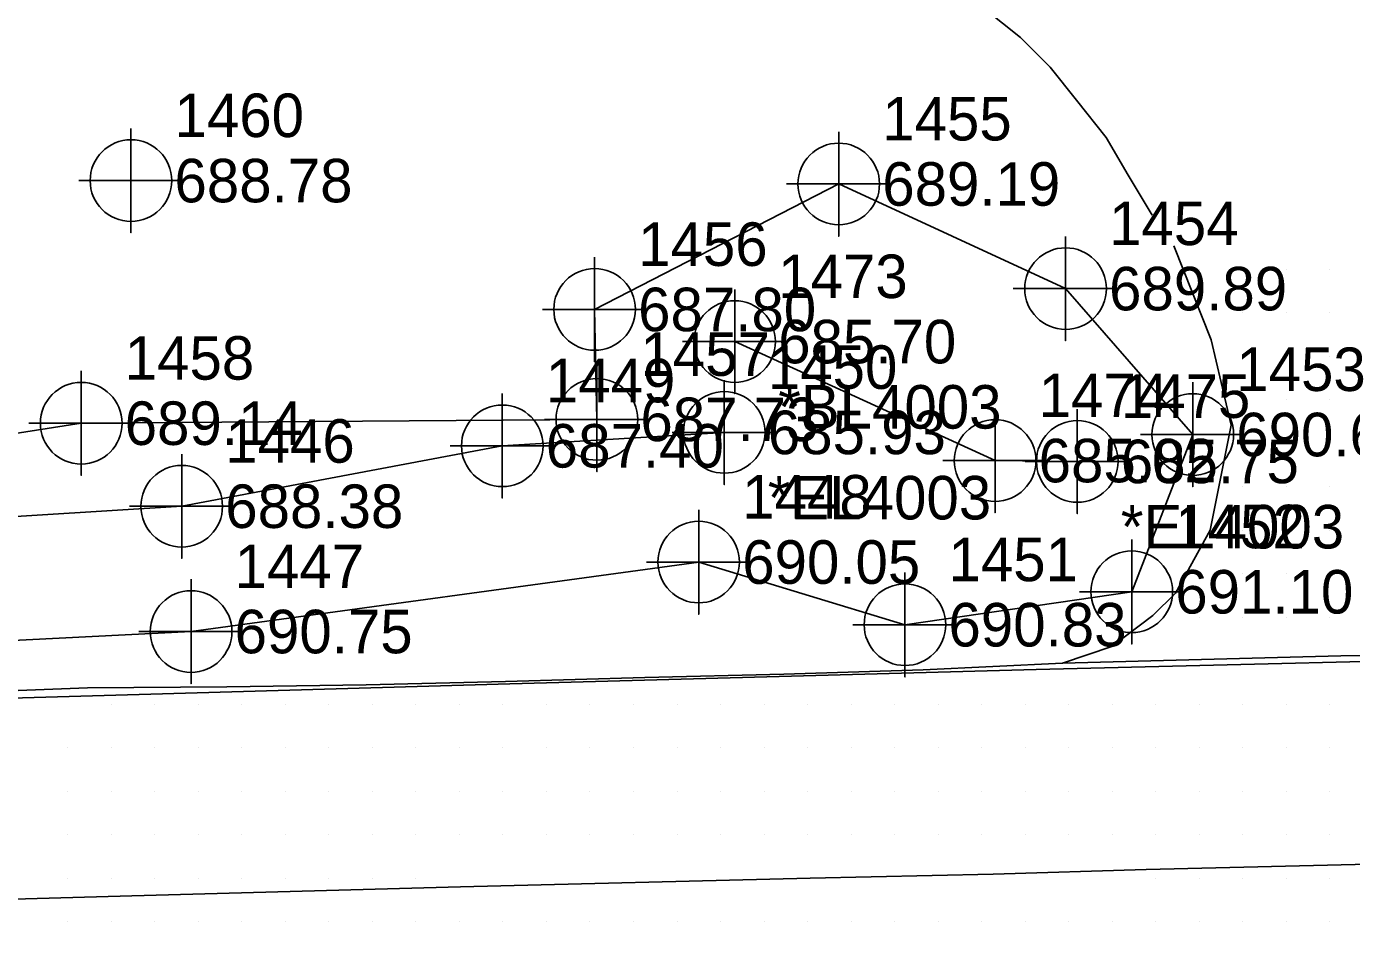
# Model space of a CAD drawing. Extents: x 1755643 to 1760494, y 736519 to 737621.
# Drawn here: x 1757941.4 to 1758017.5, y 736988 to 737040.2 of the extents above; entities that cross this region are included whole.
import ezdxf

# ---------------------------------------------------------------- set-up
doc = ezdxf.new("R2010")
doc.units = 0
for name, color, linetype in [('Exist Horizontal Alignment Curve and Spiral Data', 7, 'Continuous'), ('Exist Railroads Standard Gauge', 7, 'Continuous'), ('Exist Roads EOT', 7, 'Continuous'), ('Old_Level_1', 7, 'Continuous'), ('Old_Level_10', 7, 'Continuous'), ('Old_Level_2', 7, 'Continuous'), ('Old_Level_3', 7, 'Continuous'), ('Prop Corridor Linear Feature', 7, 'Continuous'), ('Prop Dimension', 7, 'Continuous'), ('Prop EOT Dash', 7, 'Continuous'), ('Prop Horizontal Alignment Direction Label', 7, 'Continuous'), ('Prop Lane Lines', 7, 'Continuous'), ('Prop Paved Shoulder', 7, 'Continuous'), ('Scratch_Level_1', 7, 'Continuous'), ('Scratch_Level_2', 7, 'Continuous'), ('Scratch_Level_5', 7, 'Continuous'), ('Scratch_Level_6', 7, 'Continuous'), ('Scratch_Level_9', 7, 'Continuous')]:
    doc.layers.add(name, color=color, linetype=linetype)

msp = doc.modelspace()

# ---------------------------------------------------------------- linework, layer by layer
at = {"layer": 'Exist Horizontal Alignment Curve and Spiral Data'}
msp.add_lwpolyline([(1757947.389, 737034.333), (1757947.389, 737028.333), (1757947.389, 737031.333), (1757950.389, 737031.333), (1757944.389, 737031.333)], dxfattribs=at)
msp.add_circle((1757947.389, 737031.333), 2.344, dxfattribs=at)
at = {"layer": 'Exist Railroads Standard Gauge'}
msp.add_lwpolyline([(1758006.043, 737029.342), (1758004.657, 737031.64), (1758003.404, 737033.807), (1758001.694, 737035.948), (1758000.175, 737037.856), (1757998.469, 737039.562), (1757996.412, 737041.197), (1757991.599, 737043.919), (1757989.449, 737044.86), (1757987.274, 737045.06), (1757962.295, 737044.106), (1757961.554, 737063.076)], dxfattribs=at)
at = {"layer": 'Old_Level_10'}
for points in [[(1757982.062, 737025.084), (1757982.062, 737019.084), (1757982.062, 737022.084), (1757985.062, 737022.084), (1757979.062, 737022.084)], [(1757981.467, 737019.866), (1757981.467, 737013.866), (1757981.467, 737016.866), (1757984.467, 737016.866), (1757978.467, 737016.866)], [(1757968.716, 737019.095), (1757968.716, 737013.095), (1757968.716, 737016.095), (1757971.716, 737016.095), (1757965.716, 737016.095)], [(1757997.02, 737018.248), (1757997.02, 737012.248), (1757997.02, 737015.248), (1758000.02, 737015.248), (1757994.02, 737015.248)], [(1758001.739, 737018.198), (1758001.739, 737012.198), (1758001.739, 737015.198), (1758004.739, 737015.198), (1757998.739, 737015.198)], [(1757950.306, 737015.625), (1757950.306, 737009.625), (1757950.306, 737012.625), (1757953.306, 737012.625), (1757947.306, 737012.625)]]:
    msp.add_lwpolyline(points, dxfattribs=at)
for centre in [(1757982.062, 737022.084), (1757981.467, 737016.866), (1757968.716, 737016.095), (1757997.02, 737015.248), (1758001.739, 737015.198), (1757950.306, 737012.625)]:
    msp.add_circle(centre, 2.344, dxfattribs=at)
at = {"layer": 'Prop Corridor Linear Feature'}
msp.add_lwpolyline([(1758000.882, 737003.602), (1758008.879, 737003.814), (1758016.875, 737004.021), (1758024.873, 737004.152), (1758028.534, 737004.265), (1758030.505, 737004.507)], dxfattribs=at)
at = {"layer": 'Prop Dimension'}
for points in [[(1757982.062, 737022.084), (1757997.02, 737015.248), (1758001.739, 737015.198)], [(1757921.064, 737010.807), (1757950.306, 737012.625), (1757968.716, 737016.095), (1757981.467, 737016.866)]]:
    msp.add_lwpolyline(points, dxfattribs=at)
at = {"layer": 'Prop Lane Lines'}
for points in [[(1757988.037, 737034.139), (1757988.037, 737028.139), (1757988.037, 737031.139), (1757991.037, 737031.139), (1757985.037, 737031.139)], [(1758001.065, 737028.127), (1758001.065, 737022.127), (1758001.065, 737025.127), (1758004.065, 737025.127), (1757998.065, 737025.127)], [(1757974.018, 737026.93), (1757974.018, 737020.93), (1757974.018, 737023.93), (1757977.018, 737023.93), (1757971.018, 737023.93)], [(1757944.532, 737020.395), (1757944.532, 737014.395), (1757944.532, 737017.395), (1757947.532, 737017.395), (1757941.532, 737017.395)], [(1757974.149, 737020.615), (1757974.149, 737014.615), (1757974.149, 737017.615), (1757977.149, 737017.615), (1757971.149, 737017.615)], [(1758008.37, 737019.744), (1758008.37, 737013.744), (1758008.37, 737016.744), (1758011.37, 737016.744), (1758005.37, 737016.744)], [(1757979.995, 737012.419), (1757979.995, 737006.419), (1757979.995, 737009.419), (1757982.995, 737009.419), (1757976.995, 737009.419)], [(1758004.867, 737010.71), (1758004.867, 737004.71), (1758004.867, 737007.71), (1758007.867, 737007.71), (1758001.867, 737007.71)], [(1757991.841, 737008.818), (1757991.841, 737002.818), (1757991.841, 737005.818), (1757994.841, 737005.818), (1757988.841, 737005.818)], [(1757950.843, 737008.426), (1757950.843, 737002.426), (1757950.843, 737005.426), (1757953.843, 737005.426), (1757947.843, 737005.426)]]:
    msp.add_lwpolyline(points, dxfattribs=at)
for centre in [(1757988.037, 737031.139), (1758001.065, 737025.127), (1757974.018, 737023.93), (1757944.532, 737017.395), (1757974.149, 737017.615), (1758008.37, 737016.744), (1757979.995, 737009.419), (1758004.867, 737007.71), (1757991.841, 737005.818), (1757950.843, 737005.426)]:
    msp.add_circle(centre, 2.344, dxfattribs=at)
at = {"layer": 'Scratch_Level_1'}
msp.add_lwpolyline([(1757864.939, 737000.079), (1757872.936, 737000.271), (1757880.928, 737000.627), (1757888.921, 737000.805), (1757896.919, 737000.945), (1757904.914, 737001.227), (1757912.914, 737001.293), (1757920.91, 737001.55), (1757928.913, 737001.535), (1757936.905, 737001.889), (1757944.899, 737002.192), (1757952.901, 737002.259), (1757960.901, 737002.367), (1757968.898, 737002.553), (1757976.895, 737002.778), (1757984.893, 737002.981), (1757992.889, 737003.22), (1758000.882, 737003.602)], dxfattribs=at)
at = {"layer": 'Scratch_Level_2'}
for p, q in [((1758008.75, 737026.25), (1758008.75, 737026.25)), ((1758011.25, 737026.25), (1758011.25, 737026.25)), ((1758013.75, 737026.25), (1758013.75, 737026.25)), ((1758016.25, 737026.25), (1758016.25, 737026.25)), ((1758011.25, 737023.75), (1758011.25, 737023.75)), ((1758013.75, 737023.75), (1758013.75, 737023.75)), ((1758016.25, 737023.75), (1758016.25, 737023.75)), ((1758011.25, 737021.25), (1758011.25, 737021.25)), ((1758013.75, 737021.25), (1758013.75, 737021.25)), ((1758016.25, 737021.25), (1758016.25, 737021.25)), ((1758011.25, 737018.75), (1758011.25, 737018.75)), ((1758013.75, 737018.75), (1758013.75, 737018.75)), ((1758016.25, 737018.75), (1758016.25, 737018.75)), ((1758011.25, 737016.25), (1758011.25, 737016.25)), ((1758013.75, 737016.25), (1758013.75, 737016.25)), ((1758016.25, 737016.25), (1758016.25, 737016.25)), ((1758011.25, 737013.75), (1758011.25, 737013.75)), ((1758013.75, 737013.75), (1758013.75, 737013.75)), ((1758016.25, 737013.75), (1758016.25, 737013.75)), ((1758011.25, 737011.25), (1758011.25, 737011.25)), ((1758013.75, 737011.25), (1758013.75, 737011.25)), ((1758016.25, 737011.25), (1758016.25, 737011.25)), ((1758008.75, 737008.75), (1758008.75, 737008.75)), ((1758011.25, 737008.75), (1758011.25, 737008.75)), ((1758013.75, 737008.75), (1758013.75, 737008.75)), ((1758016.25, 737008.75), (1758016.25, 737008.75)), ((1758008.75, 737006.25), (1758008.75, 737006.25)), ((1758011.25, 737006.25), (1758011.25, 737006.25)), ((1758013.75, 737006.25), (1758013.75, 737006.25)), ((1758016.25, 737006.25), (1758016.25, 737006.25)), ((1757946.25, 737001.25), (1757946.25, 737001.25)), ((1757948.75, 737001.25), (1757948.75, 737001.25)), ((1757951.25, 737001.25), (1757951.25, 737001.25)), ((1757953.75, 737001.25), (1757953.75, 737001.25)), ((1757956.25, 737001.25), (1757956.25, 737001.25)), ((1757958.75, 737001.25), (1757958.75, 737001.25)), ((1757961.25, 737001.25), (1757961.25, 737001.25)), ((1757963.75, 737001.25), (1757963.75, 737001.25)), ((1757966.25, 737001.25), (1757966.25, 737001.25)), ((1757968.75, 737001.25), (1757968.75, 737001.25)), ((1757971.25, 737001.25), (1757971.25, 737001.25)), ((1757973.75, 737001.25), (1757973.75, 737001.25)), ((1757976.25, 737001.25), (1757976.25, 737001.25)), ((1757978.75, 737001.25), (1757978.75, 737001.25)), ((1757981.25, 737001.25), (1757981.25, 737001.25)), ((1757983.75, 737001.25), (1757983.75, 737001.25)), ((1757986.25, 737001.25), (1757986.25, 737001.25)), ((1757988.75, 737001.25), (1757988.75, 737001.25)), ((1757991.25, 737001.25), (1757991.25, 737001.25)), ((1757993.75, 737001.25), (1757993.75, 737001.25)), ((1757996.25, 737001.25), (1757996.25, 737001.25)), ((1757998.75, 737001.25), (1757998.75, 737001.25)), ((1758001.25, 737001.25), (1758001.25, 737001.25)), ((1758003.75, 737001.25), (1758003.75, 737001.25)), ((1758006.25, 737001.25), (1758006.25, 737001.25)), ((1758008.75, 737001.25), (1758008.75, 737001.25)), ((1758011.25, 737001.25), (1758011.25, 737001.25)), ((1758013.75, 737001.25), (1758013.75, 737001.25)), ((1758016.25, 737001.25), (1758016.25, 737001.25)), ((1757943.75, 736998.75), (1757943.75, 736998.75)), ((1757946.25, 736998.75), (1757946.25, 736998.75)), ((1757948.75, 736998.75), (1757948.75, 736998.75)), ((1757951.25, 736998.75), (1757951.25, 736998.75)), ((1757953.75, 736998.75), (1757953.75, 736998.75)), ((1757956.25, 736998.75), (1757956.25, 736998.75)), ((1757958.75, 736998.75), (1757958.75, 736998.75)), ((1757961.25, 736998.75), (1757961.25, 736998.75)), ((1757963.75, 736998.75), (1757963.75, 736998.75)), ((1757966.25, 736998.75), (1757966.25, 736998.75)), ((1757968.75, 736998.75), (1757968.75, 736998.75)), ((1757971.25, 736998.75), (1757971.25, 736998.75)), ((1757973.75, 736998.75), (1757973.75, 736998.75)), ((1757976.25, 736998.75), (1757976.25, 736998.75)), ((1757978.75, 736998.75), (1757978.75, 736998.75)), ((1757981.25, 736998.75), (1757981.25, 736998.75)), ((1757983.75, 736998.75), (1757983.75, 736998.75)), ((1757986.25, 736998.75), (1757986.25, 736998.75)), ((1757988.75, 736998.75), (1757988.75, 736998.75)), ((1757991.25, 736998.75), (1757991.25, 736998.75)), ((1757993.75, 736998.75), (1757993.75, 736998.75)), ((1757996.25, 736998.75), (1757996.25, 736998.75)), ((1757998.75, 736998.75), (1757998.75, 736998.75)), ((1758001.25, 736998.75), (1758001.25, 736998.75)), ((1758003.75, 736998.75), (1758003.75, 736998.75)), ((1758006.25, 736998.75), (1758006.25, 736998.75)), ((1758008.75, 736998.75), (1758008.75, 736998.75)), ((1758011.25, 736998.75), (1758011.25, 736998.75)), ((1758013.75, 736998.75), (1758013.75, 736998.75)), ((1758016.25, 736998.75), (1758016.25, 736998.75)), ((1757943.75, 736996.25), (1757943.75, 736996.25)), ((1757946.25, 736996.25), (1757946.25, 736996.25)), ((1757948.75, 736996.25), (1757948.75, 736996.25)), ((1757951.25, 736996.25), (1757951.25, 736996.25)), ((1757953.75, 736996.25), (1757953.75, 736996.25)), ((1757956.25, 736996.25), (1757956.25, 736996.25)), ((1757958.75, 736996.25), (1757958.75, 736996.25)), ((1757961.25, 736996.25), (1757961.25, 736996.25)), ((1757963.75, 736996.25), (1757963.75, 736996.25)), ((1757966.25, 736996.25), (1757966.25, 736996.25)), ((1757968.75, 736996.25), (1757968.75, 736996.25)), ((1757971.25, 736996.25), (1757971.25, 736996.25)), ((1757973.75, 736996.25), (1757973.75, 736996.25)), ((1757976.25, 736996.25), (1757976.25, 736996.25)), ((1757978.75, 736996.25), (1757978.75, 736996.25)), ((1757981.25, 736996.25), (1757981.25, 736996.25)), ((1757983.75, 736996.25), (1757983.75, 736996.25)), ((1757986.25, 736996.25), (1757986.25, 736996.25)), ((1757988.75, 736996.25), (1757988.75, 736996.25)), ((1757991.25, 736996.25), (1757991.25, 736996.25)), ((1757993.75, 736996.25), (1757993.75, 736996.25)), ((1757996.25, 736996.25), (1757996.25, 736996.25)), ((1757998.75, 736996.25), (1757998.75, 736996.25)), ((1758001.25, 736996.25), (1758001.25, 736996.25)), ((1758003.75, 736996.25), (1758003.75, 736996.25)), ((1758006.25, 736996.25), (1758006.25, 736996.25)), ((1758008.75, 736996.25), (1758008.75, 736996.25)), ((1758011.25, 736996.25), (1758011.25, 736996.25)), ((1758013.75, 736996.25), (1758013.75, 736996.25)), ((1758016.25, 736996.25), (1758016.25, 736996.25)), ((1757943.75, 736993.75), (1757943.75, 736993.75)), ((1757946.25, 736993.75), (1757946.25, 736993.75)), ((1757948.75, 736993.75), (1757948.75, 736993.75)), ((1757951.25, 736993.75), (1757951.25, 736993.75)), ((1757953.75, 736993.75), (1757953.75, 736993.75)), ((1757956.25, 736993.75), (1757956.25, 736993.75)), ((1757958.75, 736993.75), (1757958.75, 736993.75)), ((1757961.25, 736993.75), (1757961.25, 736993.75)), ((1757963.75, 736993.75), (1757963.75, 736993.75)), ((1757966.25, 736993.75), (1757966.25, 736993.75)), ((1757968.75, 736993.75), (1757968.75, 736993.75)), ((1757971.25, 736993.75), (1757971.25, 736993.75)), ((1757973.75, 736993.75), (1757973.75, 736993.75)), ((1757976.25, 736993.75), (1757976.25, 736993.75)), ((1757978.75, 736993.75), (1757978.75, 736993.75)), ((1757981.25, 736993.75), (1757981.25, 736993.75)), ((1757983.75, 736993.75), (1757983.75, 736993.75)), ((1757986.25, 736993.75), (1757986.25, 736993.75)), ((1757988.75, 736993.75), (1757988.75, 736993.75)), ((1757991.25, 736993.75), (1757991.25, 736993.75)), ((1757993.75, 736993.75), (1757993.75, 736993.75)), ((1757996.25, 736993.75), (1757996.25, 736993.75)), ((1757998.75, 736993.75), (1757998.75, 736993.75)), ((1758001.25, 736993.75), (1758001.25, 736993.75)), ((1758003.75, 736993.75), (1758003.75, 736993.75)), ((1758006.25, 736993.75), (1758006.25, 736993.75)), ((1758008.75, 736993.75), (1758008.75, 736993.75)), ((1758011.25, 736993.75), (1758011.25, 736993.75)), ((1758013.75, 736993.75), (1758013.75, 736993.75)), ((1758016.25, 736993.75), (1758016.25, 736993.75)), ((1757943.75, 736991.25), (1757943.75, 736991.25)), ((1757946.25, 736991.25), (1757946.25, 736991.25)), ((1757948.75, 736991.25), (1757948.75, 736991.25)), ((1757951.25, 736991.25), (1757951.25, 736991.25)), ((1757953.75, 736991.25), (1757953.75, 736991.25)), ((1757956.25, 736991.25), (1757956.25, 736991.25)), ((1757958.75, 736991.25), (1757958.75, 736991.25)), ((1757961.25, 736991.25), (1757961.25, 736991.25)), ((1757963.75, 736991.25), (1757963.75, 736991.25)), ((1758006.25, 736991.25), (1758006.25, 736991.25)), ((1758008.75, 736991.25), (1758008.75, 736991.25)), ((1758011.25, 736991.25), (1758011.25, 736991.25)), ((1758013.75, 736991.25), (1758013.75, 736991.25)), ((1758016.25, 736991.25), (1758016.25, 736991.25)), ((1757943.75, 736988.75), (1757943.75, 736988.75)), ((1757946.25, 736988.75), (1757946.25, 736988.75)), ((1757948.75, 736988.75), (1757948.75, 736988.75)), ((1757951.25, 736988.75), (1757951.25, 736988.75)), ((1757953.75, 736988.75), (1757953.75, 736988.75)), ((1757956.25, 736988.75), (1757956.25, 736988.75)), ((1757958.75, 736988.75), (1757958.75, 736988.75)), ((1757961.25, 736988.75), (1757961.25, 736988.75)), ((1757963.75, 736988.75), (1757963.75, 736988.75)), ((1757966.25, 736988.75), (1757966.25, 736988.75)), ((1757968.75, 736988.75), (1757968.75, 736988.75)), ((1757971.25, 736988.75), (1757971.25, 736988.75)), ((1757973.75, 736988.75), (1757973.75, 736988.75)), ((1757976.25, 736988.75), (1757976.25, 736988.75)), ((1757978.75, 736988.75), (1757978.75, 736988.75)), ((1757981.25, 736988.75), (1757981.25, 736988.75)), ((1757983.75, 736988.75), (1757983.75, 736988.75)), ((1757986.25, 736988.75), (1757986.25, 736988.75)), ((1757988.75, 736988.75), (1757988.75, 736988.75)), ((1757991.25, 736988.75), (1757991.25, 736988.75)), ((1757993.75, 736988.75), (1757993.75, 736988.75)), ((1757996.25, 736988.75), (1757996.25, 736988.75)), ((1757998.75, 736988.75), (1757998.75, 736988.75)), ((1758001.25, 736988.75), (1758001.25, 736988.75)), ((1758003.75, 736988.75), (1758003.75, 736988.75)), ((1758006.25, 736988.75), (1758006.25, 736988.75)), ((1758008.75, 736988.75), (1758008.75, 736988.75)), ((1758011.25, 736988.75), (1758011.25, 736988.75)), ((1758013.75, 736988.75), (1758013.75, 736988.75)), ((1758016.25, 736988.75), (1758016.25, 736988.75))]:
    msp.add_line(p, q, dxfattribs=at)
at = {"layer": 'Scratch_Level_5'}
for points in [[(1757864.463, 736999.502), (1757881.496, 736999.898), (1757895.349, 737000.323), (1757902.806, 737000.519), (1757928.432, 737001.252), (1757948.524, 737001.834), (1757969.145, 737002.413), (1757999.376, 737003.236), (1758030.724, 737004.002), (1758039.045, 737004.185), (1758058.137, 737004.631), (1758064.691, 737004.753)], [(1757864.901, 736988.021), (1757894.4, 736988.775), (1757921.615, 736989.52), (1757947.433, 736990.242), (1757966.325, 736990.768), (1757986.395, 736991.257), (1757996.913, 736991.496), (1758005.687, 736991.753), (1758027.312, 736992.264), (1758052.981, 736992.866), (1758064.805, 736993.189)]]:
    msp.add_lwpolyline(points, dxfattribs=at)
at = {"layer": 'Scratch_Level_6'}
msp.add_lwpolyline([(1758007.286, 737027.579), (1758009.42, 737022.18), (1758010.582, 737017.289), (1758009.363, 737011.253), (1758007.378, 737007.627), (1758006.081, 737006.344), (1758003.727, 737004.576), (1758000.882, 737003.602)], dxfattribs=at)
at = {"layer": 'Scratch_Level_9'}
msp.add_lwpolyline([(1757920.884, 737003.91), (1757950.843, 737005.426), (1757979.995, 737009.419), (1757991.841, 737005.818), (1758004.867, 737007.71), (1758008.37, 737016.744), (1758001.065, 737025.127), (1757988.037, 737031.139), (1757974.018, 737023.93), (1757974.149, 737017.615), (1757944.532, 737017.395), (1757905.428, 737011.267)], dxfattribs=at)

# ---------------------------------------------------------------- texts
at = {"layer": 'Exist Roads EOT'}
msp.add_text('1460', height=2.5, dxfattribs=at).set_placement((1757949.889, 737033.833))
at = {"layer": 'Old_Level_1'}
for s, p in [('1473', (1757984.562, 737024.584)), ('1450', (1757983.967, 737019.366)), ('1449', (1757971.216, 737018.595)), ('1474', (1757999.52, 737017.748)), ('1475', (1758004.239, 737017.698)), ('1446', (1757952.806, 737015.125))]:
    msp.add_text(s, height=2.5, dxfattribs=at).set_placement(p)
at = {"layer": 'Old_Level_2'}
for s, p in [('685.70', (1757984.562, 737020.834)), ('685.93', (1757983.967, 737015.616)), ('687.40', (1757971.216, 737014.845)), ('685.02', (1757999.52, 737013.998)), ('685.75', (1758004.239, 737013.948)), ('688.38', (1757952.806, 737011.375))]:
    msp.add_text(s, height=2.5, dxfattribs=at).set_placement(p)
at = {"layer": 'Old_Level_3'}
for s, p in [('689.19', (1757990.537, 737029.889)), ('689.89', (1758003.565, 737023.877)), ('687.80', (1757976.518, 737022.68)), ('689.14', (1757947.032, 737016.145)), ('687.73', (1757976.649, 737016.365)), ('690.68', (1758010.87, 737015.494)), ('690.05', (1757982.495, 737008.169)), ('691.10', (1758007.367, 737006.46)), ('690.75', (1757953.343, 737004.176)), ('690.83', (1757994.341, 737004.568))]:
    msp.add_text(s, height=2.5, dxfattribs=at).set_placement(p)
at = {"layer": 'Prop EOT Dash'}
for s, p in [('1455', (1757990.537, 737033.639)), ('1454', (1758003.565, 737027.627)), ('1456', (1757976.518, 737026.43)), ('1458', (1757947.032, 737019.895)), ('1457', (1757976.649, 737020.115)), ('1453', (1758010.87, 737019.244)), ('1448', (1757982.495, 737011.919)), ('1452', (1758007.367, 737010.21)), ('1447', (1757953.343, 737007.926)), ('1451', (1757994.341, 737008.318))]:
    msp.add_text(s, height=2.5, dxfattribs=at).set_placement(p)
at = {"layer": 'Prop Horizontal Alignment Direction Label'}
for s, p in [('*BL4003', (1757984.562, 737017.084)), ('*EL4003', (1757983.967, 737011.866)), ('*EL4003', (1758004.239, 737010.198))]:
    msp.add_text(s, height=2.5, dxfattribs=at).set_placement(p)
at = {"layer": 'Prop Paved Shoulder'}
msp.add_text('688.78', height=2.5, dxfattribs=at).set_placement((1757949.889, 737030.083))

doc.saveas('drawing.dxf')
